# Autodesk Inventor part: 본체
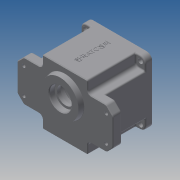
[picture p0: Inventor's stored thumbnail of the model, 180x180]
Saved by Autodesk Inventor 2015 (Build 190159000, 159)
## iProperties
Created: 2016-02
Part Number: 본체
Material: Generic
Document SubType Name: Modeling
Designer: Administrator
Density: 1 g/cm^3
Appearance: Default
Author: Administrator
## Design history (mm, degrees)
sketch "Sketch1"
  geometry: L1 (-70, -20)-(-70, 20); L2 (-33, 47)-(33, 47); L3 (70, 20)-(70, -20); L4 (70, -47)-(-70, 47); L5 (-70, -47)-(70, 47); L6 (60, 30)-(33, 30); L7 (33, 30)-(33, 47); L8 (0, 0)-(114.334, 0); L9 (0, 0)-(0, 123.01); L10 (-33, 30)-(-33, 47); L11 (-60, 30)-(-33, 30); L12 (60, -30)-(33, -30); L13 (33, -30)-(33, -47); L14 (0, 0)-(0, -123.01); L15 (-33, -47)-(33, -47); L16 (-33, -30)-(-33, -47); L17 (-60, -30)-(-33, -30); L18 (70, 20)-(60, 30); L19 (-60, 30)-(-70, 20); L20 (-70, -20)-(-60, -30); L21 (60, -30)-(70, -20); 4 further points
  constraints: 42 end point, 10 symmetric about line, 8 point on line, 2 horizontal, 2 midpoint, 1 parallel, 1 perpendicular, 1 vertical
  dimensions: "d0" = 140 distance of L4.end L5.end; "d1" = 94 distance of L5.start L4.end; "d2" = 66 distance from line of L10 L2.end; "d3" = 60 distance of point (-70, -30) point (-70, 30); "d4" = 94 distance between parallel lines of L15 L2; "d5" = 140 distance between parallel lines of L1 L3; "d6" = 10 distance of L3.start point (70, 30); "d7" = 10 distance of L6.start point (70, 30) (= d6); "d8" = 10 distance of L11.start point (-70, 30); "d9" = 10 distance of L1.end point (-70, 30) (= d8); "d10" = 10 distance of L1.start point (-70, -30) (= d8); "d11" = 10 distance of L17.start point (-70, -30) (= d10); "d12" = 10 distance of L12.start point (70, -30) (= d8); "d13" = 10 distance of L3.end point (70, -30) (= d12)
extrude "Extrusion1" new body sketch "Sketch1" distance "d14" = 13; taper "d15" = 0 deg
sketch "Sketch4"
  geometry: L1 (60, -19)-(-60, -19); L2 (-60, -19)-(-60, 19); L3 (-60, 19)-(60, 19); L4 (60, 19)-(60, -19); L5 (60, -19)-(-60, 19); L6 (-60, -19)-(60, 19); 5 further points
  constraints: 12 end point, 4 coincident, 2 midpoint, 2 parallel, 1 horizontal, 1 perpendicular
  dimensions: "d16" = 120 distance of L2.end L3.end; "d17" = 38 distance of L1.end L2.end
hole "Hole1" sketch "Sketch4" at (-60, 19), (-60, -19), (60, -19), (60, 19) diameter "d18" = 5; stored, may be unused: countersink angle "d22" = 90 deg, drill point angle "d24" = 118 deg; dims "d19" = 6, "d20" = 9, "d21" = 4, "d23" = 8
fillet "Fillet1" dims "d25" = 5
sketch "Sketch5"
  geometry: L1 (-33, -47)-(33, -47) reference; L2 (33, 47)-(-33, 47) reference; L3 (33, 35)-(33, 47) reference; L4 (-33, 47)-(-33, 35) reference; L5 (-33, -35)-(-33, -47) reference; L6 (33, -47)-(33, -35) reference; L7 (47, -30)-(47, 30); L8 (-47, -30)-(-47, 30); L9 (-60, -30)-(-38, -30) reference; L10 (38, -30)-(60, -30) reference; L11 (60, 30)-(38, 30) reference; L12 (-38, 30)-(-60, 30) reference; A1 r 5 centre (38, 35) between (33, 35) and (38, 30) reference; A2 r 5 centre (-38, 35) between (-38, 30) and (-33, 35) reference; A3 r 5 centre (-38, -35) between (-33, -35) and (-38, -30) reference; A4 r 5 centre (38, -35) between (38, -30) and (33, -35) reference; 1 further point
  constraints: 4 end point, 4 point on line, 2 vertical
  dimensions: "d26" = 47 distance from line of point (0, 0) L7; "d27" = 94 distance between parallel lines of L8 L7
extrude "Extrusion2" join sketch "Sketch5" distance "d28" = 57; taper "d29" = 0 deg
sketch "Sketch6"
  geometry: L1 (33, -47)-(-33, -47) reference; L2 (47, 30)-(47, -30) reference; L3 (-47, -30)-(-47, 30) reference; L4 (-33, 47)-(33, 47) reference; L5 (47, -30)-(47, -39); L6 (33, -47)-(39, -47); L7 (-33, -47)-(-39, -47); L8 (-47, -30)-(-47, -39); L9 (47, 30)-(47, 39); L10 (33, 47)-(39, 47); L11 (-33, 47)-(-39, 47); L12 (-47, 30)-(-47, 39); A1 r 8 centre (39, -39) between (39, -47) and (47, -39); A2 r 8 centre (-39, -39) between (-47, -39) and (-39, -47); A3 r 8 centre (-39, 39) between (-39, 47) and (-47, 39); A4 r 8 centre (39, 39) between (47, 39) and (39, 47); 1 further point
  constraints: 16 end point, 8 point on circle, 8 tangent, 4 centre point, 4 vertical, 3 equal radius, 3 horizontal, 1 perpendicular
  dimensions: "d30" = 8 radius of A1
extrude "Extrusion3" join sketch "Sketch6" distance "d31" = 10; taper "d32" = 0 deg
sketch "Sketch7"
  geometry: L1 (40, 40)-(-40, 40); L2 (-40, 40)-(-40, -40); L3 (-40, -40)-(40, -40); L4 (40, -40)-(40, 40); L5 (40, 40)-(-40, -40); L6 (-40, 40)-(40, -40); 5 further points
  constraints: 12 end point, 4 coincident, 2 midpoint, 2 parallel, 1 horizontal, 1 perpendicular
  dimensions: "d33" = 80 distance of L3.end L2.end; "d34" = 80 distance of L2.end L1.end
hole "Hole2" sketch "Sketch7" at (40, -40), (-40, -40), (-40, 40), (40, 40) diameter "d35" = 7; stored, may be unused: countersink angle "d39" = 90 deg, drill point angle "d41" = 118 deg; dims "d36" = 6, "d37" = 9, "d38" = 4, "d40" = 8
sketch "Sketch8"
  geometry: C1 r 43 at (0, 0); 1 further point
  constraints: 1 centre point, 1 coincident
  dimensions: "d42" = 86 diameter of C1
extrude "Extrusion4" cut sketch "Sketch8" distance "d43" = 9; taper "d44" = 0 deg
sketch "Sketch9"
  geometry: L1 (-39, -47)-(39, -47) reference; L2 (47, -39)-(47, 39) reference; L3 (39, 47)-(-39, 47) reference; L4 (-47, 39)-(-47, -39) reference; L5 (-35.777, -4)-(-39.799, -4); L6 (-35.777, 4)-(-39.799, 4); L7 (-42.814, 4)-(-54.27, 4); L8 (39.799, 4)-(35.777, 4); L9 (39.799, -4)-(35.777, -4); C1 r 3.5 at (-40, 40) reference; C2 r 3.5 at (40, -40) reference; C3 r 3.5 at (-40, -40) reference; C4 r 3.5 at (40, 40) reference; A1 r 8 centre (39, -39) between (39, -47) and (47, -39) reference; A2 r 8 centre (39, 39) between (47, 39) and (39, 47) reference; A3 r 8 centre (-39, 39) between (-39, 47) and (-47, 39) reference; A4 r 8 centre (-39, -39) between (-47, -39) and (-39, -47) reference; A5 r 36 centre (0, 0) between (36, 0) and (-36, 0); A6 r 4 centre (36, 0) between (36, 4) and (36, -4); A7 r 4 centre (-36, 0) between (-36, -4) and (-36, 4); A8 r 40 centre (0, 0) between (-39.799, -4) and (39.799, -4); A9 r 40 centre (0, 0) between (39.799, 4) and (-39.799, 4); 2 further points
  constraints: 14 point on circle, 10 end point, 5 centre point, 5 tangent, 4 coincident, 4 point on line, 3 perpendicular, 2 horizontal, 2 horizontal alignment, 1 equal radius, 2 other
  dimensions: "d45" = 36 radius of A5; "d46" = 4 radius of A6; "d49" = 40 radius of A8; "d50" = 40 radius of A9
extrude "Extrusion5" cut sketch "Sketch9" distance "d51" = 62; taper "d52" = 0 deg
sketch "Sketch10"
  geometry: A1 r 21 centre (0, -11) between (-12.163, 6.119) and (12.163, 6.119); A2 r 15 centre (0, 20) between (11.584, 10.47) and (-11.584, 10.47); A3 r 3 centre (13.901, 8.565) between (11.584, 10.47) and (12.163, 6.119); A4 r 3 centre (-13.901, 8.565) between (-12.163, 6.119) and (-11.584, 10.47); 1 further point
  constraints: 8 point on circle, 4 centre point, 4 tangent, 2 vertical alignment, 1 equal radius
  dimensions: "d53" = 11 distance of A1.centre point (0, 0); "d55" = 42 diameter of A1; "d56" = 15 radius of A2; "d57" = 20 distance of A2.centre point (0, 0); "d58" = 3 radius of A3
extrude "Extrusion6" join sketch "Sketch10" distance "d59" = 7; taper "d60" = 0 deg
hole "Hole3" diameter "d63" = 35; stored, may be unused: countersink angle "d67" = 90 deg, drill point angle "d69" = 0 deg; dims "d61" = 10, "d62" = 10, "d64" = 6, "d65" = 9, "d66" = 4, "d68" = 10
hole "Hole4" diameter "d72" = 19; stored, may be unused: countersink angle "d76" = 90 deg, drill point angle "d78" = 0 deg; dims "d70" = 10, "d71" = 10, "d73" = 6, "d74" = 22, "d75" = 7, "d77" = 8
sketch "Sketch11"
  geometry: C1 r 9.5 at (0, -20) reference; C2 r 28 at (0, 11); A1 r 21 centre (0, 11) between (12.163, -6.119) and (-12.163, -6.119) reference; 1 further point
  constraints: 1 centre point, 1 coincident
  dimensions: "d79" = 56 diameter of C2
extrude "Extrusion7" join sketch "Sketch11" distance "d80" = 7; taper "d81" = -10 deg
hole "Hole5" diameter "d84" = 25; stored, may be unused: countersink angle "d88" = 90 deg, drill point angle "d90" = 0 deg; dims "d82" = 10, "d83" = 10, "d85" = 6, "d86" = 32, "d87" = 8, "d89" = 8
sketch "Sketch12"
  geometry: L1 (66, 0)-(0, 0) reference; L2 (-6, 80)-(72, 80) reference; 3 further points
  constraints: 1 midpoint, 1 vertical alignment, 1 other
  dimensions: "d91" = 40 vertical distance of L2.end point (33, 40)
emboss "Emboss1" sketch "Sketch12" dims "d92" = 0.5, "d93" = 0
fillet "Fillet2" dims "d94" = 2
fillet "Fillet3" dims "d95" = 2
fillet "Fillet6" dims "d98" = 2
fillet "Fillet7" dims "d99" = 0.3
fillet "Fillet8" dims "d100" = 0.3
fillet "Fillet9" dims "d101" = 1
chamfer "Chamfer1" distance "d102" = 1; stored, may be unused: second distance "d103" = 2, angle "d104" = 45 deg
hole "Hole6" diameter "d109" = 3.242; stored, may be unused: countersink angle "d113" = 90 deg, drill point angle "d115" = 118 deg; dims "d107" = 10, "d108" = 10, "d110" = 7, "d111" = 4, "d112" = 2, "d114" = 9
hole "Hole7" diameter "d118" = 3.242; stored, may be unused: countersink angle "d122" = 90 deg, drill point angle "d124" = 118 deg; dims "d116" = 10, "d117" = 10, "d119" = 7, "d120" = 4, "d121" = 2, "d123" = 9
fillet "Fillet12" dims "d125" = 5
chamfer "Chamfer2" distance "d126" = 1; stored, may be unused: second distance "d127" = 2, angle "d128" = 45 deg
chamfer "Chamfer3" distance "d129" = 1; stored, may be unused: second distance "d130" = 2, angle "d131" = 45 deg
fillet "Fillet13" dims "d132" = 3.5
fillet "Fillet15" dims "d134" = 2
fillet "Fillet16" dims "d135" = 0.3
body "Solid1"
node "Projected Loop1"
